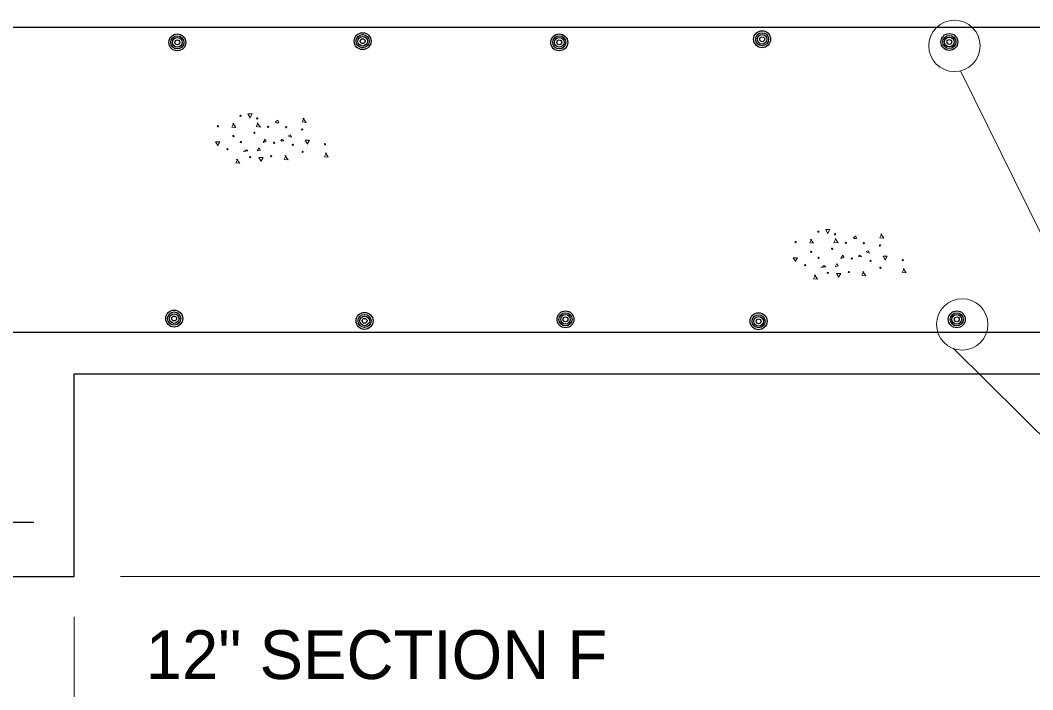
# Model space of a CAD drawing. Extents: x -28.1 to 13.9, y -16.1 to 13.9.
# Drawn here: x -6.926 to -4.33, y -12.515 to -10.799 of the extents above; entities that cross this region are included whole.
import ezdxf

# ---------------------------------------------------------------- set-up
doc = ezdxf.new("R2010")
doc.units = 0
doc.header["$LTSCALE"] = 0.05
doc.layers.add('1', color=7, linetype='Continuous', lineweight=13)
doc.layers.add('2', color=7, linetype='Continuous', lineweight=13)

msp = doc.modelspace()

# ---------------------------------------------------------------- linework, layer by layer
at = {"layer": '1', "lineweight": 25}
for p, q in [((-8.78204, -10.81631), (-2.84404, -10.81631)), ((-8.77404, -11.59831), (-2.84304, -11.59831)), ((-6.78704, -12.22431), (-6.78704, -11.70531)), ((-6.78704, -11.70531), (-2.77004, -11.70531)), ((-7.46204, -12.08531), (-6.89104, -12.08531)), ((-7.62904, -12.22431), (-6.78704, -12.22431))]:
    msp.add_line(p, q, dxfattribs=at)
at = {"layer": '1'}
for p, q in [((-3.81304, -12.35331), (-4.51504, -10.92831)), ((-3.81304, -12.35331), (-4.53304, -11.64031)), ((-6.66904, -12.22431), (-1.33704, -12.22431)), ((-6.78704, -12.32831), (-6.78704, -12.78131))]:
    msp.add_line(p, q, dxfattribs=at)
for centre in [(-4.53104, -10.86431), (-4.51104, -11.57831)]:
    msp.add_circle(centre, 0.0658, dxfattribs=at)
at = {"layer": '1', "lineweight": 25}
for centre, radius in [((-6.52299, -10.85523), 0.02168), ((-6.52299, -10.85523), 0.01681), ((-6.52299, -10.85523), 0.01233), ((-6.52299, -10.85523), 0.00623), ((-6.04799, -10.85223), 0.02168), ((-6.04799, -10.85223), 0.01681), ((-6.04799, -10.85223), 0.01233), ((-6.04799, -10.85223), 0.00623), ((-5.54399, -10.85523), 0.02168), ((-5.54399, -10.85523), 0.01681), ((-5.54399, -10.85523), 0.01233), ((-5.54399, -10.85523), 0.00623), ((-5.02399, -10.84723), 0.02168), ((-5.02399, -10.84723), 0.01681), ((-5.02399, -10.84723), 0.01233), ((-5.02399, -10.84723), 0.00623), ((-4.54399, -10.85423), 0.02168), ((-4.54399, -10.85423), 0.01681), ((-4.54399, -10.85423), 0.01233), ((-4.54399, -10.85423), 0.00623), ((-6.53099, -11.56323), 0.02168), ((-6.53099, -11.56323), 0.01681), ((-6.04299, -11.56923), 0.02168), ((-5.52799, -11.56523), 0.02168), ((-5.52799, -11.56523), 0.01681), ((-5.03299, -11.57023), 0.02168), ((-4.52499, -11.56523), 0.02168), ((-4.52499, -11.56523), 0.01681), ((-6.53099, -11.56323), 0.01233), ((-6.53099, -11.56323), 0.00623), ((-6.04299, -11.56923), 0.01681), ((-6.04299, -11.56923), 0.01233), ((-6.04299, -11.56923), 0.00623), ((-5.52799, -11.56523), 0.01233), ((-5.52799, -11.56523), 0.00623), ((-5.03299, -11.57023), 0.01681), ((-5.03299, -11.57023), 0.01233), ((-5.03299, -11.57023), 0.00623), ((-4.52499, -11.56523), 0.01233), ((-4.52499, -11.56523), 0.00623)]:
    msp.add_circle(centre, radius, dxfattribs=at)
at = {"layer": '2'}
for p, q in [((-6.27104, -11.05931), (-6.26504, -11.05431)), ((-4.79004, -11.35631), (-4.78404, -11.35131))]:
    msp.add_line(p, q, dxfattribs=at)
for points in [[(-6.33704, -11.04731), (-6.34204, -11.03831), (-6.33104, -11.03831), (-6.33704, -11.04931)], [(-6.26504, -11.05431), (-6.26304, -11.06131), (-6.27104, -11.06131)], [(-6.19804, -11.04931), (-6.20304, -11.05931), (-6.19304, -11.06031), (-6.20104, -11.04931)], [(-6.37804, -11.06231), (-6.38304, -11.07231), (-6.37304, -11.07331), (-6.38104, -11.06231)], [(-6.31604, -11.06131), (-6.32104, -11.07131), (-6.31004, -11.07231), (-6.31804, -11.06131)], [(-6.25804, -11.10731), (-6.25504, -11.10331), (-6.25004, -11.10731), (-6.25704, -11.10831)], [(-6.23804, -11.09431), (-6.23304, -11.09231), (-6.23004, -11.09831), (-6.23804, -11.09531)], [(-6.19004, -11.11431), (-6.19504, -11.10631), (-6.18404, -11.10631), (-6.19004, -11.11631)], [(-6.42004, -11.11831), (-6.42504, -11.11031), (-6.41404, -11.11031), (-6.42004, -11.12031)], [(-6.35104, -11.13331), (-6.34604, -11.13031), (-6.34204, -11.13331), (-6.35404, -11.13531)], [(-6.36804, -11.15431), (-6.37304, -11.16431), (-6.36304, -11.16531), (-6.37104, -11.15431)], [(-6.30904, -11.15931), (-6.31404, -11.15031), (-6.30304, -11.15031), (-6.30904, -11.16031)], [(-6.24404, -11.14531), (-6.24904, -11.15531), (-6.23904, -11.15631), (-6.24704, -11.14531)], [(-6.14104, -11.13831), (-6.14604, -11.14831), (-6.13604, -11.14931), (-6.14304, -11.13831)], [(-4.85604, -11.34431), (-4.86104, -11.33531), (-4.85004, -11.33531), (-4.85604, -11.34631)], [(-4.89704, -11.35931), (-4.90204, -11.36931), (-4.89204, -11.37031), (-4.90004, -11.35931)], [(-4.83504, -11.35831), (-4.84004, -11.36831), (-4.82904, -11.36931), (-4.83704, -11.35831)], [(-4.78404, -11.35131), (-4.78204, -11.35831), (-4.79004, -11.35831)], [(-4.71704, -11.34631), (-4.72204, -11.35631), (-4.71204, -11.35731), (-4.72004, -11.34631)], [(-4.75704, -11.39131), (-4.75204, -11.38931), (-4.74904, -11.39531), (-4.75704, -11.39231)], [(-4.93904, -11.41531), (-4.94404, -11.40731), (-4.93304, -11.40731), (-4.93904, -11.41731)], [(-4.77704, -11.40431), (-4.77404, -11.40031), (-4.76904, -11.40431), (-4.77604, -11.40531)], [(-4.70904, -11.41131), (-4.71404, -11.40331), (-4.70304, -11.40331), (-4.70904, -11.41331)], [(-4.87004, -11.43031), (-4.86504, -11.42731), (-4.86104, -11.43031), (-4.87304, -11.43231)], [(-4.76304, -11.44231), (-4.76804, -11.45231), (-4.75804, -11.45331), (-4.76604, -11.44231)], [(-4.66004, -11.43531), (-4.66504, -11.44531), (-4.65504, -11.44631), (-4.66204, -11.43531)], [(-4.88704, -11.45131), (-4.89204, -11.46131), (-4.88204, -11.46231), (-4.89004, -11.45131)], [(-4.82804, -11.45631), (-4.83304, -11.44731), (-4.82204, -11.44731), (-4.82804, -11.45731)]]:
    msp.add_lwpolyline(points, dxfattribs=at)
for points in [[(-6.30304, -11.11231), (-6.29804, -11.10331), (-6.29504, -11.10931)], [(-6.31804, -11.13331), (-6.31304, -11.12531), (-6.31004, -11.13131)], [(-4.82204, -11.40931), (-4.81704, -11.40031), (-4.81404, -11.40631)], [(-4.83704, -11.43031), (-4.83204, -11.42231), (-4.82904, -11.42831)]]:
    msp.add_lwpolyline(points, close=True, dxfattribs=at)
for centre in [(-6.36079, -11.04344), (-6.31804, -11.05019), (-6.41904, -11.07019), (-6.29029, -11.07194), (-6.24404, -11.07294), (-6.20279, -11.07869), (-6.37929, -11.09544), (-6.32554, -11.08719), (-6.39454, -11.12919), (-6.36004, -11.11069), (-6.27504, -11.11244), (-6.22704, -11.11819), (-6.20179, -11.13594), (-6.14454, -11.11644), (-6.33654, -11.14944), (-6.28254, -11.14694), (-4.87979, -11.34044), (-4.93804, -11.36719), (-4.83704, -11.34719), (-4.80929, -11.36894), (-4.89829, -11.39244), (-4.84454, -11.38419), (-4.76304, -11.36994), (-4.72179, -11.37569), (-4.87904, -11.40769), (-4.79404, -11.40944), (-4.74604, -11.41519), (-4.66354, -11.41344), (-4.91354, -11.42619), (-4.85554, -11.44644), (-4.80154, -11.44394), (-4.72079, -11.43294)]:
    msp.add_circle(centre, 0.00162, dxfattribs=at)

# ---------------------------------------------------------------- texts
at = {"layer": '1'}
msp.add_text('12" SECTION F', height=0.125, dxfattribs=at).set_placement((-6.60404, -12.48731))

doc.saveas('drawing.dxf')
